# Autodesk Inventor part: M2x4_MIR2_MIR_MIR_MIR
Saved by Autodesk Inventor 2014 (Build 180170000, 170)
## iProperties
Created: 2015-05
Part Number: M2x4_MIR2_MIR_MIR_MIR
Material: 일반
Vendor: CBT Solutions
Document SubType Name: 모델링
Designer: Administrator
Appearance: 기본값
Company: 한국ATC센터
Author: KYOUNG IL JANG
Comments: 파생
d0: 1.000 ul
d0_1: 1.000 ul
d0_1_1: 1.000 ul
d0_1_1_1: 1.000 ul
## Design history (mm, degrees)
derived "M2x4_MIR2_MIR_MIR.ipt"
feature "솔리드1::M2x4_MIR2_MIR_MIR.ipt"
tag "피쳐 태그1"
node "솔리드1"
other parameters: "d0" = 1, "d0_1" = 1, "d0_1_1" = 1, "d0_1_1_1" = 1
